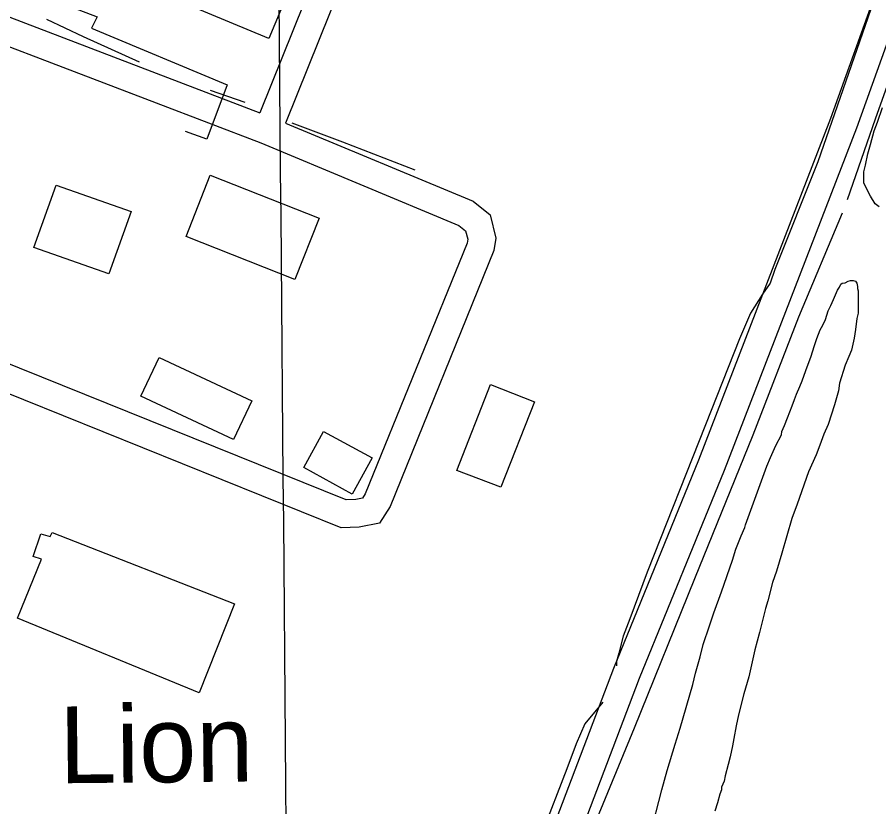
# Model space of a CAD drawing. Extents: x 3567028 to 3605064, y 510945 to 536587.
# Drawn here: x 3592043 to 3592975, y 517875 to 518730 of the extents above; entities that cross this region are included whole.
import ezdxf

# ---------------------------------------------------------------- set-up
doc = ezdxf.new("R2010")
doc.units = 0
for name, color, linetype in [('V-BLDG-IDEN', 7, 'Continuous'), ('V-BLDG-OTLN', 7, 'Continuous'), ('V-GRID-MAJR', 7, 'Continuous'), ('V-ROAD-CNTR', 7, 'Continuous'), ('V-SITE-VEGE', 7, 'Continuous'), ('V-TOPO-SHOR', 7, 'Continuous'), ('V-UTIL-LINE', 7, 'Continuous')]:
    doc.layers.add(name, color=color, linetype=linetype)

msp = doc.modelspace()

# ---------------------------------------------------------------- linework, layer by layer
at = {"layer": 'V-BLDG-OTLN'}
for points in [[(3592204.83, 518854.73), (3592351.72, 518793.41), (3592315.54, 518706.73), (3592168.64, 518768.04)], [(3592343.56, 518445.92), (3592225.92, 518492.57), (3592252.19, 518558.82), (3592369.83, 518512.17)], [(3592061.4, 518480.65), (3592085.28, 518548.15), (3592166.41, 518519.46), (3592142.53, 518451.96)], [(3592277.39, 518272.51), (3592177.04, 518319.44), (3592196.7, 518361.47), (3592297.04, 518314.54)], [(3592518.93, 518239.26), (3592555.44, 518332.05), (3592602.87, 518313.38), (3592566.48, 518220.92)], [(3592405.71, 518213.62), (3592353.24, 518242.3), (3592374.67, 518281.51), (3592427.14, 518252.84)], [(3592081.23, 518172.17), (3592278.28, 518094.84), (3592240.17, 517998.55), (3592043.68, 518079.25), (3592069.46, 518143.07), (3592060.5, 518145.87), (3592068.91, 518170.5), (3592078.99, 518167.7)]]:
    msp.add_lwpolyline(points, close=True, dxfattribs=at)
at = {"layer": 'V-GRID-MAJR'}
msp.add_spline([(3592345.91, 516527.14), (3592293.93, 522584.81), (3592241.91, 528645.56), (3592189.9, 534706.32), (3592189.88, 534709.39)], degree=3, dxfattribs=at)
at = {"layer": 'V-ROAD-CNTR'}
for points in [[(3592721.04, 520433.27), (3593078.19, 520285.29), (3593296.9, 520190.95), (3593329.78, 520166.89), (3593347.92, 520150.96), (3593370.46, 520124.22), (3593388.5, 520098.72), (3593403.25, 520068.15), (3593408.23, 520044.8), (3593409.24, 520021.29), (3593410.22, 519981.49), (3593401.22, 519934.9), (3593305, 519651.94), (3593165.71, 519235.39), (3593032.53, 518836.44), (3592951.2, 518609.66), (3592808.18, 518239.24), (3592716.31, 518013.98), (3592582.74, 517662.42), (3592458.21, 517365.18), (3592335.4, 517029.66), (3592195.48, 516654.6), (3592147.82, 516523.52)], [(3592710.13, 520405.32), (3593066.51, 520257.66), (3593281.91, 520164.75), (3593310.99, 520143.47), (3593326.43, 520129.91), (3593346.7, 520105.86), (3593362.57, 520083.43), (3593374.67, 520058.36), (3593378.37, 520041), (3593379.25, 520020.28), (3593380.15, 519983.99), (3593372.16, 519942.61), (3593276.57, 519661.53), (3593137.26, 519244.89), (3593004.18, 518846.26), (3592923.08, 518620.13), (3592780.29, 518250.31), (3592688.39, 518024.97), (3592554.87, 517673.55), (3592516.49, 517581.93)], [(3592110.91, 518914.61), (3592213.75, 518873.24), (3592377.79, 518805.98), (3592305.8, 518626.28)], [(3592405.61, 518794.74), (3592333.64, 518615.09)], [(3592035.33, 518729.8), (3592305.8, 518626.28)], [(3592023.47, 518702.22), (3592306.84, 518593.76), (3592521.09, 518504.49), (3592528.25, 518498.67), (3592530.65, 518489.4), (3592529.97, 518485.35), (3592419.84, 518213.96), (3592416.83, 518209.16), (3592409.67, 518207.73), (3592399.1, 518207.27), (3591974.72, 518378.52), (3591900.06, 518404.1)], [(3592333.64, 518615.09), (3592536.64, 518530.51), (3592554.82, 518515.73), (3592561.28, 518490.76), (3592559.02, 518477.15), (3592446.65, 518200.26), (3592435.4, 518182.29), (3592413.28, 518177.85), (3592393.9, 518177.02), (3591964.24, 518350.4), (3591889.01, 518376.17)]]:
    msp.add_lwpolyline(points, dxfattribs=at)
at = {"layer": 'V-SITE-VEGE'}
for points in [[(3592975.8, 518524.37), (3592971.68, 518527.9), (3592966.39, 518536.14), (3592959.34, 518550.25), (3592959.35, 518562.6), (3592961.11, 518569.65), (3592963.47, 518582), (3592966.41, 518591.99), (3592970.54, 518606.69), (3592974.07, 518616.1), (3592979.37, 518631.97)], [(3592854.16, 518243.75), (3592858.28, 518253.15), (3592864.16, 518266.09), (3592870.05, 518277.84), (3592870.64, 518281.37), (3592873.58, 518287.84), (3592876.52, 518296.07), (3592881.82, 518309), (3592884.17, 518316.06), (3592886.53, 518321.93), (3592890.06, 518330.17), (3592892.41, 518336.04), (3592896.53, 518347.22), (3592898.89, 518354.27), (3592901.83, 518361.91), (3592905.95, 518374.26), (3592908.31, 518381.9), (3592911.84, 518391.31), (3592914.78, 518396.6), (3592917.72, 518402.48), (3592920.66, 518411.88), (3592923.6, 518417.76), (3592926.55, 518424.23), (3592930.67, 518434.22), (3592933.02, 518437.75), (3592934.2, 518440.69), (3592935.96, 518441.86), (3592938.9, 518442.45), (3592942.43, 518444.22), (3592944.78, 518444.8), (3592947.72, 518444.8), (3592950.08, 518444.21), (3592951.84, 518441.86), (3592952.42, 518438.33), (3592952.42, 518435.98), (3592953.01, 518433.63), (3592953, 518409.52), (3592951.82, 518403.64), (3592950.05, 518391.88), (3592948.88, 518382.47), (3592945.93, 518369.54), (3592942.99, 518362.49), (3592938.87, 518353.08), (3592932.98, 518333.68), (3592931.8, 518325.45), (3592927.68, 518310.16), (3592920.62, 518289), (3592915.91, 518278.42), (3592911.79, 518266.66), (3592907.67, 518256.08)], [(3592907.67, 518256.08), (3592899.43, 518237.85), (3592887.07, 518202.58), (3592881.18, 518187.29), (3592870.59, 518149.66), (3592864.7, 518130.26), (3592860.58, 518117.92), (3592855.28, 518097.93), (3592852.93, 518089.7), (3592846.45, 518063.83), (3592841.15, 518045.02), (3592834.67, 518015.62), (3592829.37, 517997.39), (3592823.48, 517974.46), (3592821.13, 517962.7), (3592818.77, 517949.18), (3592817, 517940.95), (3592814.65, 517929.19), (3592812.29, 517920.96), (3592809.35, 517908.62), (3592808.17, 517902.73), (3592805.23, 517896.27), (3592805.23, 517893.33), (3592803.46, 517888.63), (3592801.1, 517879.22), (3592798.16, 517870.4)], [(3592728.18, 517844.55), (3592740.55, 517893.35), (3592746.44, 517914.52), (3592755.27, 517942.74), (3592760.56, 517960.38), (3592774.11, 518007.41), (3592777.05, 518019.76), (3592782.35, 518037.39), (3592785.29, 518050.92), (3592792.36, 518070.9), (3592797.07, 518085.01), (3592805.31, 518107.94), (3592817.08, 518142.04), (3592820.61, 518153.8), (3592826.5, 518168.49), (3592830.62, 518177.31), (3592831.21, 518180.26), (3592854.16, 518243.75)]]:
    msp.add_lwpolyline(points, dxfattribs=at)
at = {"layer": 'V-TOPO-SHOR'}
msp.add_line((3592290.04, 518637.61), (3592252.32, 518650.6), dxfattribs=at)
for points in [[(3593375.87, 519818.39), (3593361.05, 519765.72), (3593328.44, 519665.12), (3593286.34, 519540.26), (3593238.31, 519398.24), (3593184.37, 519247.35), (3593138.12, 519108.87), (3593080.61, 518941.41), (3593030.8, 518785.77), (3592971.52, 518619.49), (3592941.34, 518532.28)], [(3593297.69, 519713.08), (3593257.96, 519596.51), (3593248.24, 519568.55), (3593202.83, 519437.92), (3593155.98, 519296.49), (3593098.48, 519126.65), (3593067.97, 519038.56), (3593010.69, 518870.28), (3592966.66, 518738.46), (3592909.34, 518573.36), (3592863.11, 518456.79), (3592857.77, 518441.99), (3592849.48, 518430.16), (3592836.45, 518409.45), (3592824.6, 518381.64), (3592787.85, 518288.74), (3592725.01, 518128.97), (3592706.04, 518078.67), (3592698.93, 518059.73), (3592694.19, 518041.39), (3592691.81, 518032.51), (3592691.81, 518027.78)], [(3592175.7, 518681.3), (3592115, 518708.45), (3592075.52, 518727.34)], [(3592473.92, 518564.41), (3592395.54, 518594.52), (3592340.72, 518615.18)], [(3592935.95, 518517.71), (3592888.53, 518405.28), (3592839.33, 518277.46), (3592775.91, 518121.84), (3592710.71, 517960.29), (3592653.22, 517820.05), (3592618.24, 517728.33), (3592576.16, 517612.94)], [(3592676.99, 517988.45), (3592657.37, 517964.91), (3592647.86, 517943.35), (3592637.78, 517916.3), (3592610.73, 517846.13), (3592576.97, 517762.77), (3592568.53, 517736.65), (3592555.49, 517697), (3592551.93, 517685.76), (3592550.74, 517682.2)]]:
    msp.add_lwpolyline(points, dxfattribs=at)
at = {"layer": 'V-UTIL-LINE'}
msp.add_lwpolyline([(3591983.2, 518792.06), (3592002.4, 518781.07), (3591998.27, 518768.04), (3592018.16, 518761.86), (3592053.14, 518744), (3592067.55, 518754.28), (3592129.96, 518730.24), (3592123.78, 518717.89), (3592270.54, 518656.76), (3592248.56, 518597.77), (3592225.24, 518606.02)], dxfattribs=at)

# ---------------------------------------------------------------- texts
at = {"layer": 'V-BLDG-IDEN'}
msp.add_text('Lion', height=83, rotation=0.55499, dxfattribs=at).set_placement((3592089.2, 517900.53))

doc.saveas('drawing.dxf')
